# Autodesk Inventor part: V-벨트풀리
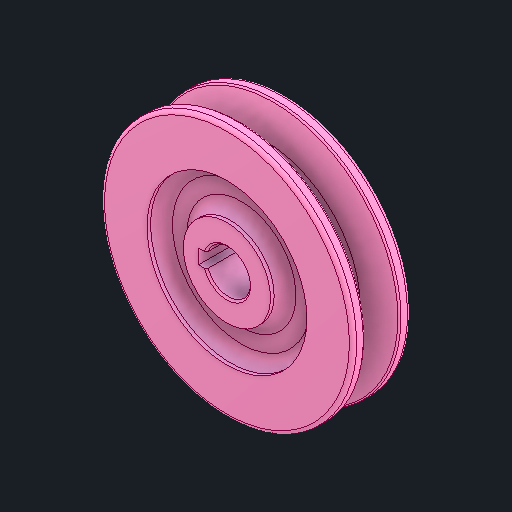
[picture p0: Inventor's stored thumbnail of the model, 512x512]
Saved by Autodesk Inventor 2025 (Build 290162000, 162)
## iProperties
Created: 2025-08
Part Number: V-벨트풀리
Material: 강철, 연강
Document SubType Name: Modeling
Designer: infra08
Density: 7.86 g/cm^3
Appearance: 기본값
Author: jhkim
Sending System: Autodesk Inventor 2026
Preprocessor: ST-DEVELOPER v20.1
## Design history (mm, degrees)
feature "Solid1"
node "솔리드1"
